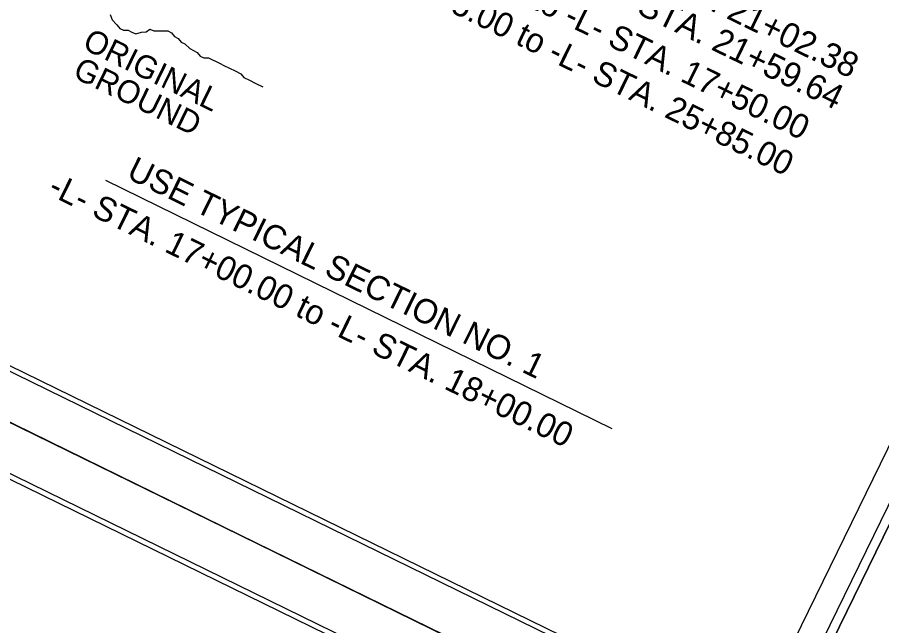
# Model space of a CAD drawing. Extents: x 1518247 to 1523638, y 635234 to 639927.
# Drawn here: x 1522074.1 to 1522497.7, y 638278.9 to 638576.7 of the extents above; entities that cross this region are included whole.
import ezdxf

# ---------------------------------------------------------------- set-up
doc = ezdxf.new("R2010")
doc.units = 0
for name, color, linetype in [('Default', 7, 'Continuous'), ('Sheet Cutting Line CELL', 7, 'Continuous'), ('Sheet Plot Border Inside CELL', 7, 'Continuous'), ('Sheet Plot Border Outside CELL', 7, 'Continuous'), ('Sheet Typical CELL', 7, 'Continuous'), ('Typical Hinge Slope Interstate CELL', 7, 'Continuous'), ('Typical Pavement Slope CELL', 7, 'Continuous'), ('Typical Text Label CELL', 7, 'Continuous')]:
    doc.layers.add(name, color=color, linetype=linetype)

msp = doc.modelspace()

# ---------------------------------------------------------------- linework, layer by layer
at = {"layer": 'Default'}
for points in [[(1522438.02, 638198.63), (1520925.25, 638938.49), (1521408.53, 639926.64), (1522921.3, 639186.78)], [(1520441.97, 637950.34), (1521954.73, 637210.48), (1522438.02, 638198.63), (1520925.25, 638938.49)]]:
    msp.add_lwpolyline(points, close=True, dxfattribs=at)
at = {"layer": 'Sheet Cutting Line CELL'}
for p, q in [((1520925.25, 638938.49), (1522438.02, 638198.63)), ((1522438.02, 638198.63), (1520925.25, 638938.49))]:
    msp.add_line(p, q, dxfattribs=at)
at = {"layer": 'Sheet Plot Border Inside CELL'}
for points in [[(1522907.39, 639168.59), (1521410.35, 639900.76), (1520946.79, 638952.95), (1522443.84, 638220.77)], [(1522424.11, 638180.44), (1520927.06, 638912.61), (1520463.51, 637964.8), (1521960.55, 637232.62)]]:
    msp.add_lwpolyline(points, close=True, dxfattribs=at)
at = {"layer": 'Sheet Plot Border Outside CELL'}
for points in [[(1522921.3, 639186.78), (1521408.53, 639926.64), (1520925.25, 638938.49), (1522438.02, 638198.63)], [(1522438.02, 638198.63), (1520925.25, 638938.49), (1520441.97, 637950.34), (1521954.73, 637210.48)]]:
    msp.add_lwpolyline(points, close=True, dxfattribs=at)
at = {"layer": 'Sheet Typical CELL'}
for points in [[(1522895.04, 639171.79), (1521547.57, 639830.81), (1521086.25, 638887.58), (1522433.73, 638228.56)], [(1522411.76, 638183.64), (1521064.29, 638842.66), (1520602.97, 637899.43), (1521950.45, 637240.41)]]:
    msp.add_lwpolyline(points, close=True, dxfattribs=at)
at = {"layer": 'Typical Hinge Slope Interstate CELL'}
msp.add_lwpolyline([(1522119.6, 638578.18), (1522120.54, 638575.41), (1522122.88, 638573.12), (1522124.28, 638571.27), (1522126.14, 638570.36), (1522128.45, 638570.39), (1522130.31, 638569.48), (1522132.17, 638568.57), (1522134.93, 638569.51), (1522137.25, 638569.54), (1522139.09, 638570.94), (1522140.95, 638570.03), (1522143.26, 638570.04), (1522145.57, 638570.06), (1522147.88, 638570.09), (1522149.74, 638569.18), (1522151.14, 638567.33), (1522153, 638566.42), (1522154.4, 638564.58), (1522156.26, 638563.67), (1522158.59, 638561.38), (1522160.45, 638560.47), (1522162.31, 638559.56), (1522163.71, 638557.72), (1522165.57, 638556.81), (1522167.88, 638556.83), (1522169.74, 638555.92), (1522171.59, 638555.01), (1522173.45, 638554.1), (1522175.31, 638553.19), (1522178.1, 638551.82), (1522180.88, 638550.46), (1522183.67, 638549.09), (1522185.07, 638547.25), (1522187.85, 638545.89), (1522190.64, 638544.52), (1522194.36, 638542.7)], dxfattribs=at)
at = {"layer": 'Typical Text Label CELL'}
msp.add_line((1522117.37, 638497.04), (1522365.5, 638375.46), dxfattribs=at)

# ---------------------------------------------------------------- texts
at = {"layer": 'Typical Hinge Slope Interstate CELL'}
for s, p in [('ORIGINAL', (1522105.5, 638561.65)), ('GROUND', (1522100.76, 638547.61))]:
    msp.add_text(s, height=11.211, rotation=334.0511, dxfattribs=at).set_placement(p)
at = {"layer": 'Typical Pavement Slope CELL'}
for s, height, rotation, p in [('-Y- STA. 16+71.30 to -Y- STA. 21+02.38', 12.1642, 334.0511, (1522219.07, 638674.79)), ('-Y- STA. 21+02.38 to -Y- STA. 21+59.64', 12.1642, 334.0511, (1522211.61, 638659.45)), ('-L- STA. 17+00.00 to -L- STA. 17+50.00', 11.8983, 333.8962, (1522204.3, 638640.89)), ('-L- STA. 25+35.00 to -L- STA. 25+85.00', 11.8983, 333.8962, (1522196.49, 638623.31)), ('-L- STA. 17+00.00 to -L- STA. 18+00.00', 11.8983, 333.8962, (1522088.54, 638490.29))]:
    msp.add_text(s, height=height, rotation=rotation, dxfattribs=at).set_placement(p)
at = {"layer": 'Typical Text Label CELL'}
msp.add_text('USE TYPICAL SECTION NO. 1', height=11.8983, rotation=333.8962, dxfattribs=at).set_placement((1522127.08, 638498.29))

doc.saveas('drawing.dxf')
